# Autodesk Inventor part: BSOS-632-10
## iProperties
Author: Ron Crain
Shininess: 25.0
Angle Display Precision: 2
Document Length Units: 11272
Document Angle Units: 11286
Document Time Units: 11279
Document Mass Units: 11290
Document Length Units Precision: 3
Document Angle Units Precision: 2
Compacted: True
PropertySet Name: _Private Model Information
Created: 2001-09
Part Number: BSOS-632-10
Material: Stainless Steel, Austenitic
Description: STANDOFF, BLIND, SELF CLINCH, 6-32 UNC X 0.3125
Vendor: PENN ENG. & MFG
Document SubType Name: Modeling
Designer: Ron Crain
Control State: 0
Master: False
Checked Out: False
PropertySet Name: Design Tracking Control
Density: 7.84
Volumn: 0.17245559573138858
Area: 3.4800931280430336
PropertySet Name: Model Information
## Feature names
1. Extrusion1
2. Extrusion2
3. Revolution1
4. Revolution2
5. Rectangular Pattern1
6. Hole1
7. Chamfer3
8. Chamfer4
